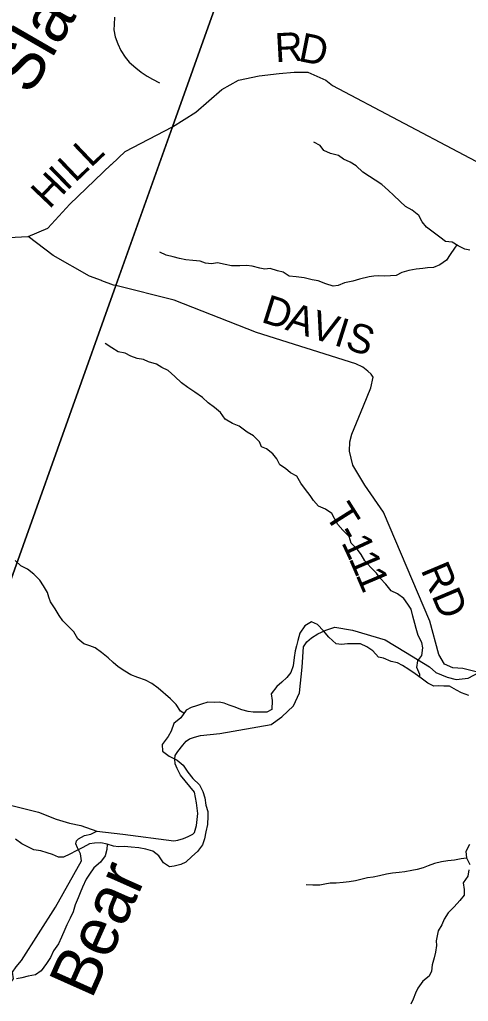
# Model space of a CAD drawing. Extents: x 1624196 to 2029251, y 146837 to 440034.
# Drawn here: x 1772378 to 1777038, y 291903 to 302092 of the extents above; entities that cross this region are included whole.
import ezdxf

# ---------------------------------------------------------------- set-up
doc = ezdxf.new("R2010")
doc.units = 0
for name, color, linetype in [('GM_X_County_Road', 7, 'Continuous'), ('GM_X_County_Road_Text', 7, 'Continuous'), ('GM_X_Minor_River', 7, 'Continuous'), ('GM_X_Minor_River_Text', 7, 'Continuous'), ('GM_X_Township', 7, 'Continuous'), ('GM_X_Township_Road', 7, 'Continuous'), ('GM_X_Township_Road_Text', 7, 'Continuous')]:
    doc.layers.add(name, color=color, linetype=linetype)

msp = doc.modelspace()

# ---------------------------------------------------------------- linework, layer by layer
at = {"layer": 'GM_X_County_Road'}
for points in [[(1773330, 300587), (1773331, 300588), (1773472, 300722), (1773964, 300978), (1774207, 301130), (1774479, 301368), (1774650, 301465), (1774866, 301509), (1775073, 301534), (1775230, 301546), (1775370, 301546), (1775556, 301465), (1775626, 301409), (1777673, 300329)], [(1772261, 299832), (1772262, 299832), (1772468, 299842), (1772670, 299926), (1772900, 300177), (1773330, 300587)], [(1773180, 293671), (1773448, 293638), (1773980, 293570), (1774019, 293576), (1774078, 293594), (1774128, 293615), (1774175, 293639), (1774194, 293656), (1774213, 293729), (1774229, 293854), (1774216, 293964), (1774193, 294073), (1774050, 294252), (1774014, 294321), (1773992, 294368), (1773989, 294417), (1773994, 294454), (1774019, 294498), (1774071, 294562), (1774108, 294603), (1774143, 294628), (1774193, 294646), (1774257, 294662), (1774457, 294684), (1774991, 294775), (1775101, 294855), (1775220, 294971), (1775284, 295107), (1775311, 295371), (1775327, 295584), (1775359, 295633), (1775409, 295676), (1775475, 295718), (1775556, 295756), (1775652, 295786), (1775836, 295755), (1776173, 295654), (1776385, 295527), (1776635, 295376), (1776700, 295318), (1776818, 295267), (1776912, 295245), (1777036, 295259), (1777146, 295317)], [(1772149, 292014), (1772154, 292017), (1772193, 292034), (1772236, 292053), (1772282, 292097), (1772314, 292137), (1772305, 292205), (1772343, 292263), (1772397, 292327), (1772752, 292882), (1773022, 293362), (1773010, 293434), (1772978, 293495), (1772960, 293539), (1772967, 293568), (1772988, 293591), (1773050, 293625), (1773116, 293639), (1773180, 293671)]]:
    msp.add_lwpolyline(points, dxfattribs=at)
at = {"layer": 'GM_X_Minor_River'}
for points in [[(1773363, 302119), (1773358, 302043), (1773356, 301985), (1773370, 301913), (1773397, 301842), (1773429, 301770), (1773474, 301702), (1773516, 301649), (1773584, 301591), (1773639, 301548), (1773701, 301504), (1773757, 301473), (1773831, 301437)], [(1777053, 299701), (1777001, 299708), (1776931, 299745), (1776868, 299781), (1776800, 299790), (1776740, 299834), (1776671, 299885), (1776603, 299938), (1776558, 299994), (1776522, 300060), (1776453, 300113), (1776383, 300154), (1776328, 300204), (1776260, 300269), (1776207, 300317), (1776139, 300382), (1776068, 300427), (1776010, 300465), (1775940, 300510), (1775871, 300573), (1775811, 300611), (1775742, 300644), (1775688, 300682), (1775606, 300703), (1775538, 300734), (1775497, 300786), (1775433, 300819)], [(1776916, 299754), (1776895, 299719), (1776849, 299653), (1776810, 299597), (1776742, 299546), (1776674, 299520), (1776614, 299517), (1776564, 299509), (1776497, 299502), (1776419, 299490), (1776345, 299467), (1776287, 299437), (1776229, 299432), (1776165, 299430), (1776109, 299433), (1776057, 299431), (1776007, 299422), (1775907, 299398), (1775837, 299379), (1775751, 299362), (1775686, 299332), (1775634, 299327), (1775559, 299351), (1775479, 299380), (1775417, 299392), (1775333, 299411), (1775249, 299422), (1775177, 299429), (1775116, 299471), (1775054, 299486), (1774980, 299510), (1774924, 299503), (1774872, 299513), (1774791, 299534), (1774733, 299540), (1774663, 299537), (1774577, 299538), (1774511, 299552), (1774433, 299567), (1774371, 299559), (1774309, 299564), (1774251, 299584), (1774177, 299593), (1774103, 299600), (1774038, 299614), (1773972, 299629), (1773900, 299647), (1773834, 299680)], [(1776532, 295269), (1776532, 295297), (1776504, 295368), (1776513, 295436), (1776553, 295493), (1776566, 295573), (1776555, 295629), (1776515, 295702), (1776494, 295774), (1776482, 295826), (1776461, 295901), (1776442, 295975), (1776410, 296027), (1776367, 296084), (1776303, 296134), (1776235, 296163), (1776180, 296233), (1776122, 296296), (1776083, 296346), (1776025, 296405), (1775964, 296474), (1775923, 296542), (1775885, 296594), (1775820, 296657), (1775798, 296729), (1775735, 296792), (1775681, 296854), (1775646, 296913), (1775620, 296967), (1775553, 297010), (1775481, 297042), (1775428, 297103), (1775394, 297153), (1775345, 297216), (1775299, 297282), (1775256, 297353), (1775190, 297389), (1775139, 297432), (1775079, 297472), (1775047, 297535), (1775008, 297587), (1774940, 297636), (1774889, 297660), (1774869, 297710), (1774806, 297771), (1774742, 297810), (1774658, 297872), (1774587, 297901), (1774513, 297946), (1774462, 298016), (1774400, 298067), (1774337, 298115), (1774275, 298172), (1774198, 298227), (1774124, 298275), (1774059, 298324), (1773991, 298387), (1773920, 298451), (1773856, 298480), (1773800, 298516), (1773717, 298541), (1773663, 298564), (1773599, 298574), (1773533, 298599), (1773475, 298631), (1773402, 298644), (1773336, 298685), (1773266, 298731)], [(1774084, 294893), (1774048, 294915), (1774002, 294984), (1773943, 295044), (1773818, 295153), (1773752, 295202), (1773685, 295237), (1773605, 295265), (1773533, 295292), (1773469, 295330), (1773402, 295375), (1773350, 295420), (1773297, 295468), (1773227, 295523), (1773162, 295573), (1773106, 295594), (1773044, 295614), (1772981, 295667), (1772939, 295737), (1772882, 295798), (1772826, 295854), (1772789, 295909), (1772747, 295977), (1772698, 296048), (1772680, 296098), (1772667, 296148), (1772627, 296215), (1772588, 296273), (1772524, 296338), (1772459, 296390), (1772389, 296423), (1772332, 296477)], [(1777042, 295079), (1776966, 295107), (1776914, 295132), (1776841, 295174), (1776783, 295173), (1776731, 295177), (1776679, 295176), (1776615, 295206), (1776547, 295257), (1776484, 295304), (1776420, 295348), (1776355, 295389), (1776301, 295415), (1776235, 295432), (1776157, 295466), (1776103, 295477), (1776044, 295540), (1775984, 295582), (1775917, 295613), (1775839, 295615), (1775783, 295614), (1775719, 295606), (1775663, 295615), (1775589, 295682), (1775532, 295750), (1775471, 295813), (1775407, 295841), (1775339, 295800), (1775288, 295726), (1775265, 295650), (1775253, 295594), (1775240, 295540), (1775230, 295472), (1775217, 295386), (1775195, 295318), (1775154, 295266), (1775100, 295215), (1775049, 295171), (1774991, 295096), (1775000, 295025), (1774995, 294931), (1774945, 294906), (1774877, 294906), (1774803, 294905), (1774751, 294911), (1774685, 294930), (1774606, 294959), (1774554, 294977), (1774502, 294997), (1774450, 295010), (1774400, 295004), (1774332, 295007), (1774266, 294989), (1774214, 294972), (1774158, 294952), (1774108, 294927), (1774051, 294847), (1773979, 294787), (1773952, 294708), (1773919, 294652), (1773859, 294570), (1773860, 294500), (1773932, 294449), (1774013, 294407), (1774075, 294356), (1774126, 294283), (1774178, 294215)], [(1774178, 294215), (1774247, 294150), (1774280, 294080), (1774302, 294014), (1774311, 293941), (1774333, 293875), (1774332, 293825), (1774328, 293739), (1774311, 293663), (1774296, 293589), (1774276, 293529), (1774225, 293457), (1774165, 293408), (1774104, 293348), (1774052, 293323), (1773984, 293305), (1773934, 293300), (1773872, 293342), (1773823, 293415), (1773761, 293461), (1773690, 293482), (1773616, 293498), (1773536, 293503), (1773468, 293512), (1773404, 293508), (1773352, 293515), (1773286, 293535), (1773222, 293548), (1773156, 293546), (1773104, 293539), (1773034, 293501), (1772966, 293464), (1772898, 293430), (1772833, 293401), (1772781, 293399), (1772720, 293428), (1772664, 293444), (1772598, 293465), (1772526, 293475), (1772456, 293512), (1772399, 293539), (1772335, 293585)], [(1773286, 293535), (1773282, 293481), (1773265, 293415), (1773219, 293348), (1773148, 293290), (1773104, 293224), (1773067, 293172), (1773031, 293087), (1773006, 293031), (1772984, 292979), (1772953, 292905), (1772933, 292833), (1772902, 292767), (1772867, 292699), (1772847, 292648), (1772812, 292568), (1772780, 292500), (1772731, 292428), (1772697, 292360), (1772658, 292295), (1772603, 292219), (1772541, 292179), (1772467, 292166), (1772399, 292146), (1772347, 292137)], [(1777049, 293530), (1777012, 293460), (1777017, 293394), (1777051, 293322)], [(1777019, 293390), (1776963, 293383), (1776895, 293369), (1776823, 293362), (1776757, 293350), (1776685, 293333), (1776621, 293309), (1776567, 293290), (1776507, 293272), (1776449, 293263), (1776378, 293249), (1776318, 293242), (1776250, 293234), (1776186, 293225), (1776114, 293207), (1776048, 293192), (1775990, 293184), (1775920, 293169), (1775866, 293155), (1775798, 293144), (1775738, 293138), (1775666, 293129), (1775604, 293130), (1775548, 293120), (1775496, 293108), (1775424, 293109), (1775354, 293112)], [(1777044, 293270), (1777032, 293204), (1776985, 293132), (1776995, 293066), (1776994, 293004), (1776950, 292950), (1776889, 292885), (1776829, 292823), (1776786, 292755), (1776762, 292697), (1776725, 292634), (1776713, 292582), (1776704, 292532), (1776708, 292482), (1776695, 292414), (1776681, 292354), (1776662, 292282), (1776656, 292218), (1776629, 292166), (1776565, 292114), (1776514, 292042), (1776490, 291987), (1776465, 291927), (1776439, 291873)]]:
    msp.add_lwpolyline(points, dxfattribs=at)
at = {"layer": 'GM_X_Township'}
for points in [[(1775883, 306354), (1773964, 300978), (1773376, 299332), (1771450, 293936)], [(1771450, 293936), (1773376, 299332), (1773964, 300978), (1775883, 306354)]]:
    msp.add_lwpolyline(points, dxfattribs=at)
at = {"layer": 'GM_X_Township_Road'}
for points in [[(1773230, 299382), (1773229, 299383), (1773105, 299428), (1772725, 299644), (1772468, 299842)], [(1777146, 295317), (1776979, 295359), (1776875, 295364), (1776791, 295404), (1776731, 295504), (1776636, 295849), (1776155, 296979), (1775961, 297260), (1775838, 297469), (1775804, 297613), (1775808, 297710), (1775829, 297790), (1775947, 298084), (1776024, 298272), (1776048, 298381), (1776028, 298413), (1775993, 298445), (1775940, 298486), (1775870, 298519), (1774839, 298845), (1773982, 299182), (1773376, 299332), (1773352, 299337), (1773230, 299382)], [(1771473, 293914), (1771623, 294027), (1771656, 294042), (1771700, 294048), (1771775, 294049), (1771979, 294020), (1772243, 293951), (1772573, 293868), (1772757, 293794), (1772896, 293753), (1773012, 293729), (1773180, 293671)]]:
    msp.add_lwpolyline(points, dxfattribs=at)

# ---------------------------------------------------------------- texts
at = {"layer": 'GM_X_County_Road_Text'}
for s, rotation, p in [('R', 3.1668, (1775036, 301650)), ('D', 348.6629, (1775262, 301665)), ('L', 43.6423, (1773116, 300548)), ('I', 44.2273, (1772866, 300307)), ('L', 43.6938, (1772954, 300393)), ('H', 46.4169, (1772686, 300118))]:
    msp.add_text(s, height=300, rotation=rotation, dxfattribs=at).set_placement(p)
at = {"layer": 'GM_X_Minor_River_Text'}
for s, rotation, p in [('Slate', 59.9991, (1772489, 301295)), ('Bear', 65.9975, (1773125, 291915))]:
    msp.add_text(s, height=500, rotation=rotation, dxfattribs=at).set_placement(p)
at = {"layer": 'GM_X_Township_Road_Text'}
for s, rotation, p in [('D', 342.4498, (1774875, 298957)), ('A', 342.4511, (1775126, 298877)), ('V', 342.4532, (1775378, 298797)), ('I', 342.4043, (1775630, 298718)), ('S', 341.7063, (1775746, 298681)), ('T', 302.2789, (1775541, 296956)), ('-', 298.6081, (1775658, 296770)), ('1', 294.9373, (1775715, 296667)), ('1', 293.1019, (1775792, 296501)), ('1', 293.1019, (1775864, 296331)), ('RD', 292.8102, (1776540, 296382))]:
    msp.add_text(s, height=300, rotation=rotation, dxfattribs=at).set_placement(p)

doc.saveas('drawing.dxf')
